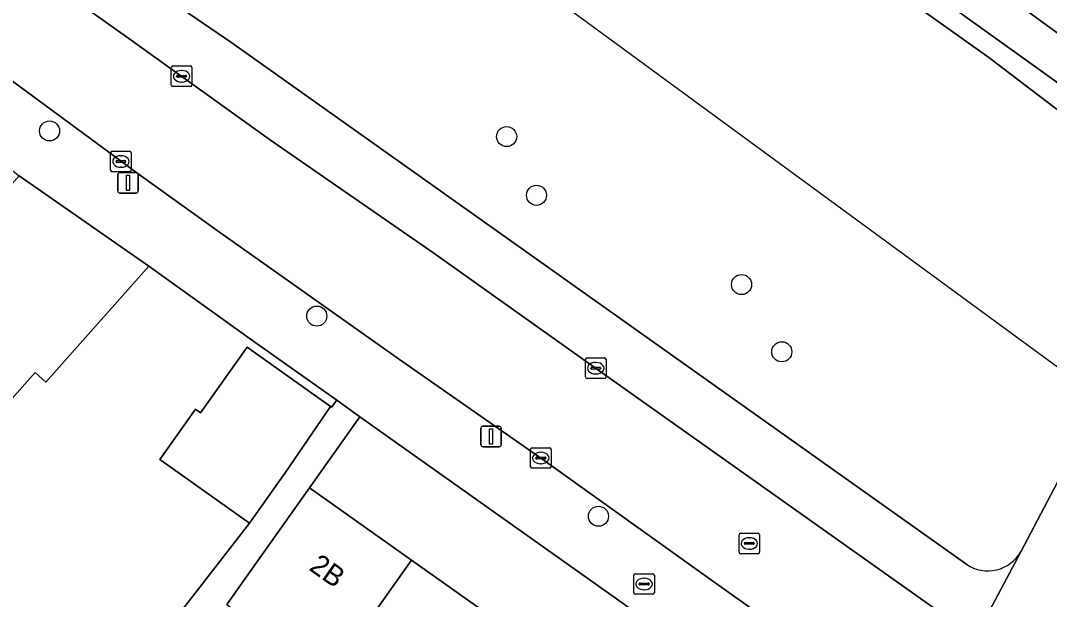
# Model space of a CAD drawing. Extents: x 162803 to 163818, y 381639 to 382475.
# Drawn here: x 162952.8 to 163002.9, y 382037.7 to 382065.9 of the extents above; entities that cross this region are included whole.
import ezdxf

# ---------------------------------------------------------------- set-up
doc = ezdxf.new("R2010")
doc.units = 0
for name, color, linetype in [('IMGEO_Boom', 7, 'Continuous'), ('IMGEO_Brandkraan', 7, 'Continuous'), ('IMGEO_Duiker', 7, 'Continuous'), ('IMGEO_Erf', 7, 'Continuous'), ('IMGEO_Groenvoorziening', 7, 'Continuous'), ('IMGEO_Haag', 7, 'Continuous'), ('IMGEO_Kolk', 7, 'Continuous'), ('IMGEO_Lichtmast', 7, 'Continuous'), ('IMGEO_Pand', 7, 'Continuous'), ('IMGEO_Pand_nummerreeks', 7, 'Continuous'), ('IMGEO_Rijbaan_lokaal_open', 7, 'Continuous'), ('IMGEO_Rioolput', 7, 'Continuous'), ('IMGEO_Voetpad_gesloten', 7, 'Continuous'), ('IMGEO_Voetpad_open', 7, 'Continuous')]:
    doc.layers.add(name, color=color, linetype=linetype)

msp = doc.modelspace()

# ---------------------------------------------------------------- linework, layer by layer
at = {"layer": 'IMGEO_Boom'}
for centre in [(162954.211, 382060.563), (162976.49, 382060.288), (162977.945, 382057.429), (162987.94, 382053.084), (162967.237, 382051.546), (162989.901, 382049.806), (162980.966, 382041.796)]:
    msp.add_circle(centre, 0.489, dxfattribs=at)
at = {"layer": 'IMGEO_Brandkraan'}
for p, q in [((162982.69, 382038.07), (162982.69, 382038.922)), ((162982.765, 382038.996), (162983.617, 382038.996)), ((162983.178, 382038.776), (162983.203, 382038.776)), ((162983.691, 382038.922), (162983.691, 382038.07)), ((162982.949, 382038.49), (162982.949, 382038.502)), ((162983.387, 382038.453), (162982.989, 382038.453)), ((162982.992, 382038.539), (162983.39, 382038.539)), ((162983.433, 382038.502), (162983.433, 382038.49)), ((162983.617, 382037.996), (162982.765, 382037.996)), ((162983.201, 382038.216), (162983.176, 382038.216))]:
    msp.add_line(p, q, dxfattribs=at)
for points in [[(162982.69, 382038.07), (162982.69, 382038.922)], [(162982.765, 382038.996), (162983.617, 382038.996)], [(162983.691, 382038.922), (162983.691, 382038.07)], [(162983.617, 382037.996), (162982.765, 382037.996)]]:
    msp.add_lwpolyline(points, dxfattribs=at)
for centre, radius, start, end in [((162982.767, 382038.92), 0.0765, 91.552, 178.448), ((162982.767, 382038.92), 0.0765, 91.552, 178.448), ((162983.615, 382038.92), 0.0765, 1.552, 88.448), ((162983.615, 382038.92), 0.0765, 1.552, 88.448), ((162982.989, 382038.499), 0.0403, 85.8775, 175.7526), ((162982.986, 382038.489), 0.0366, 178.938, 274.7102), ((162983.39, 382038.496), 0.043, 264.8664, 352.4533), ((162983.394, 382038.501), 0.0386, 1.7309, 96.639), ((162982.767, 382038.072), 0.0765, 181.552, 268.448), ((162982.767, 382038.072), 0.0765, 181.552, 268.448), ((162983.615, 382038.072), 0.0765, 271.552, 358.448), ((162983.615, 382038.072), 0.0765, 271.552, 358.448)]:
    msp.add_arc(centre, radius, start, end, dxfattribs=at)
for centre, major_axis, ratio, start_param, end_param in [((162983.177, 382038.496), (-0.387, 0.002), 0.722429, 4.712389, 7.853982), ((162983.202, 382038.496), (-0.39, 0.002), 0.717154, 1.570796, 4.712389)]:
    msp.add_ellipse(centre, major_axis=major_axis, ratio=ratio, start_param=start_param, end_param=end_param, dxfattribs=at)
at = {"layer": 'IMGEO_Duiker'}
msp.add_lwpolyline([(163005.466, 382047.505), (162974.599, 382070.108), (162970.901, 382072.816), (162970.703, 382072.961)], dxfattribs=at)
at = {"layer": 'IMGEO_Erf'}
msp.add_lwpolyline([(162958.614, 382034.766), (162959.507, 382035.735), (162963.96, 382041.461), (162959.584, 382044.562), (162961.318, 382047.008), (162961.57, 382046.829), (162963.835, 382050.026), (162967.902, 382047.144), (162967.96, 382047.103), (162968.205, 382047.449), (162964.058, 382050.389), (162959.047, 382053.976), (162954.036, 382048.329), (162953.503, 382048.802), (162949.504, 382044.283), (162949.355, 382044.115), (162945.432, 382039.695), (162941.189, 382034.913), (162937.377, 382030.619), (162933.576, 382026.335), (162932.914, 382025.589), (162929.595, 382021.849)], dxfattribs=at)
msp.add_lwpolyline([(162969.337, 382046.646), (162966.877, 382043.183), (162971.85, 382039.659), (162976.524, 382036.346), (162981.522, 382032.804), (162986.518, 382029.263), (162991.153, 382025.978), (162995.918, 382022.601), (163000, 382019.705), (163000.963, 382019.023), (163006.032, 382015.435), (163008.484, 382018.885), (163000, 382024.908)], close=True, dxfattribs=at)
at = {"layer": 'IMGEO_Groenvoorziening'}
for points in [[(163000, 382064.141), (162988.306, 382072.452), (162975.64, 382081.142), (162964.013, 382088.892), (162957.595, 382092.972), (162957.972, 382093.775), (162955.509, 382095.286), (162955.095, 382094.405), (162947.756, 382098.312), (162942.304, 382100.629), (162935.833, 382102.859), (162935.503, 382103.431), (162934.025, 382103.793), (162930.797, 382104.582), (162926.669, 382103.516), (162926.014, 382103.347), (162923.417, 382102.535), (162923.386, 382102.523), (162920.985, 382101.569), (162918.543, 382100.297)], [(162955.06, 382095.576), (162955.509, 382095.286), (162957.972, 382093.775), (162966.406, 382088.6), (162979.279, 382080.171), (163010.771, 382057.59), (163010.938, 382058.34)], [(162917.77, 382093.992), (162952.869, 382071.831), (162963.101, 382064.851), (162998.912, 382039.447)], [(163010.057, 382060.459), (162995.864, 382070.771)], [(163001.555, 382040.071), (163005.466, 382047.505), (163010.153, 382056.414), (163000, 382064.141)]]:
    msp.add_lwpolyline(points, dxfattribs=at)
msp.add_lwpolyline([(162979.279, 382080.171), (162966.406, 382088.6), (162957.972, 382093.775), (162957.595, 382092.972), (162964.013, 382088.892), (162975.64, 382081.142), (162988.306, 382072.452), (163000, 382064.141), (163010.153, 382056.414), (163010.771, 382057.59)], close=True, dxfattribs=at)
msp.add_arc((162999.941, 382040.996), 1.86, 236.3975, 330.1705, dxfattribs=at)
at = {"layer": 'IMGEO_Haag'}
msp.add_lwpolyline([(162979.279, 382080.171), (162966.406, 382088.6), (162957.972, 382093.775), (162957.595, 382092.972), (162964.013, 382088.892), (162975.64, 382081.142), (162988.306, 382072.452), (163000, 382064.141), (163010.153, 382056.414), (163010.771, 382057.59)], close=True, dxfattribs=at)
at = {"layer": 'IMGEO_Kolk'}
for p, q in [((162960.146, 382062.801), (162960.146, 382063.653)), ((162960.221, 382063.727), (162961.073, 382063.727)), ((162960.634, 382063.507), (162960.659, 382063.507)), ((162961.147, 382063.653), (162961.147, 382062.801)), ((162960.405, 382063.221), (162960.405, 382063.233)), ((162960.843, 382063.184), (162960.445, 382063.184)), ((162960.448, 382063.27), (162960.846, 382063.27)), ((162960.657, 382062.947), (162960.632, 382062.947)), ((162960.889, 382063.233), (162960.889, 382063.221)), ((162961.073, 382062.727), (162960.221, 382062.727)), ((162957.188, 382058.65), (162957.188, 382059.502)), ((162957.263, 382059.576), (162958.115, 382059.576)), ((162957.676, 382059.356), (162957.701, 382059.356)), ((162958.189, 382059.502), (162958.189, 382058.65)), ((162957.447, 382059.07), (162957.447, 382059.082)), ((162957.885, 382059.033), (162957.487, 382059.033)), ((162957.49, 382059.119), (162957.888, 382059.119)), ((162957.699, 382058.796), (162957.674, 382058.796)), ((162957.931, 382059.082), (162957.931, 382059.07)), ((162958.115, 382058.576), (162957.263, 382058.576)), ((162980.333, 382048.581), (162980.333, 382049.433)), ((162980.408, 382049.507), (162981.26, 382049.507)), ((162980.821, 382049.287), (162980.846, 382049.287)), ((162981.334, 382049.433), (162981.334, 382048.581)), ((162980.592, 382049.001), (162980.592, 382049.013)), ((162981.03, 382048.964), (162980.632, 382048.964)), ((162980.635, 382049.05), (162981.033, 382049.05)), ((162981.076, 382049.013), (162981.076, 382049.001)), ((162981.26, 382048.507), (162980.408, 382048.507)), ((162980.844, 382048.727), (162980.819, 382048.727)), ((162977.655, 382044.208), (162977.655, 382045.06)), ((162977.73, 382045.134), (162978.582, 382045.134)), ((162978.143, 382044.914), (162978.168, 382044.914)), ((162978.656, 382045.06), (162978.656, 382044.208)), ((162977.914, 382044.628), (162977.914, 382044.64)), ((162978.352, 382044.591), (162977.954, 382044.591)), ((162977.957, 382044.677), (162978.355, 382044.677)), ((162978.166, 382044.354), (162978.141, 382044.354)), ((162978.398, 382044.64), (162978.398, 382044.628)), ((162978.582, 382044.134), (162977.73, 382044.134))]:
    msp.add_line(p, q, dxfattribs=at)
for points in [[(162960.146, 382062.801), (162960.146, 382063.653)], [(162960.221, 382063.727), (162961.073, 382063.727)], [(162961.147, 382063.653), (162961.147, 382062.801)], [(162961.073, 382062.727), (162960.221, 382062.727)], [(162957.188, 382058.65), (162957.188, 382059.502)], [(162957.263, 382059.576), (162958.115, 382059.576)], [(162958.189, 382059.502), (162958.189, 382058.65)], [(162958.115, 382058.576), (162957.263, 382058.576)], [(162980.333, 382048.581), (162980.333, 382049.433)], [(162980.408, 382049.507), (162981.26, 382049.507)], [(162981.334, 382049.433), (162981.334, 382048.581)], [(162981.26, 382048.507), (162980.408, 382048.507)], [(162977.655, 382044.208), (162977.655, 382045.06)], [(162977.73, 382045.134), (162978.582, 382045.134)], [(162978.656, 382045.06), (162978.656, 382044.208)], [(162978.582, 382044.134), (162977.73, 382044.134)]]:
    msp.add_lwpolyline(points, dxfattribs=at)
for centre, radius, start, end in [((162960.223, 382063.651), 0.0765, 91.552, 178.448), ((162960.223, 382063.651), 0.0765, 91.552, 178.448), ((162961.071, 382063.651), 0.0765, 1.552, 88.448), ((162961.071, 382063.651), 0.0765, 1.552, 88.448), ((162960.445, 382063.23), 0.0403, 85.8775, 175.7526), ((162960.442, 382063.22), 0.0366, 178.938, 274.7102), ((162960.846, 382063.227), 0.043, 264.8664, 352.4533), ((162960.85, 382063.232), 0.0386, 1.7309, 96.639), ((162960.223, 382062.803), 0.0765, 181.552, 268.448), ((162960.223, 382062.803), 0.0765, 181.552, 268.448), ((162961.071, 382062.803), 0.0765, 271.552, 358.448), ((162961.071, 382062.803), 0.0765, 271.552, 358.448), ((162957.265, 382059.5), 0.0765, 91.552, 178.448), ((162957.265, 382059.5), 0.0765, 91.552, 178.448), ((162958.113, 382059.5), 0.0765, 1.552, 88.448), ((162958.113, 382059.5), 0.0765, 1.552, 88.448), ((162957.487, 382059.079), 0.0403, 85.8775, 175.7526), ((162957.484, 382059.069), 0.0366, 178.938, 274.7102), ((162957.888, 382059.076), 0.043, 264.8664, 352.4533), ((162957.892, 382059.081), 0.0386, 1.7309, 96.639), ((162957.265, 382058.652), 0.0765, 181.552, 268.448), ((162957.265, 382058.652), 0.0765, 181.552, 268.448), ((162958.113, 382058.652), 0.0765, 271.552, 358.448), ((162958.113, 382058.652), 0.0765, 271.552, 358.448), ((162980.41, 382049.431), 0.0765, 91.552, 178.448), ((162980.41, 382049.431), 0.0765, 91.552, 178.448), ((162981.258, 382049.431), 0.0765, 1.552, 88.448), ((162981.258, 382049.431), 0.0765, 1.552, 88.448), ((162980.632, 382049.01), 0.0403, 85.8775, 175.7526), ((162980.629, 382049), 0.0366, 178.938, 274.7102), ((162981.033, 382049.007), 0.043, 264.8664, 352.4533), ((162981.037, 382049.012), 0.0386, 1.7309, 96.639), ((162980.41, 382048.583), 0.0765, 181.552, 268.448), ((162980.41, 382048.583), 0.0765, 181.552, 268.448), ((162981.258, 382048.583), 0.0765, 271.552, 358.448), ((162981.258, 382048.583), 0.0765, 271.552, 358.448), ((162977.732, 382045.058), 0.0765, 91.552, 178.448), ((162977.732, 382045.058), 0.0765, 91.552, 178.448), ((162978.58, 382045.058), 0.0765, 1.552, 88.448), ((162978.58, 382045.058), 0.0765, 1.552, 88.448), ((162977.954, 382044.637), 0.0403, 85.8775, 175.7526), ((162977.951, 382044.627), 0.0366, 178.938, 274.7102), ((162978.355, 382044.634), 0.043, 264.8664, 352.4533), ((162978.359, 382044.639), 0.0386, 1.7309, 96.639), ((162977.732, 382044.21), 0.0765, 181.552, 268.448), ((162977.732, 382044.21), 0.0765, 181.552, 268.448), ((162978.58, 382044.21), 0.0765, 271.552, 358.448), ((162978.58, 382044.21), 0.0765, 271.552, 358.448)]:
    msp.add_arc(centre, radius, start, end, dxfattribs=at)
for centre, major_axis, ratio, start_param, end_param in [((162960.633, 382063.227), (-0.387, 0.002), 0.722429, 4.712389, 7.853982), ((162960.658, 382063.227), (-0.39, 0.002), 0.717154, 1.570796, 4.712389), ((162957.675, 382059.076), (-0.387, 0.002), 0.722429, 4.712389, 7.853982), ((162957.7, 382059.076), (-0.39, 0.002), 0.717154, 1.570796, 4.712389), ((162980.82, 382049.007), (-0.387, 0.002), 0.722429, 4.712389, 7.853982), ((162980.845, 382049.007), (-0.39, 0.002), 0.717154, 1.570796, 4.712389), ((162978.142, 382044.634), (-0.387, 0.002), 0.722429, 4.712389, 7.853982), ((162978.167, 382044.634), (-0.39, 0.002), 0.717154, 1.570796, 4.712389)]:
    msp.add_ellipse(centre, major_axis=major_axis, ratio=ratio, start_param=start_param, end_param=end_param, dxfattribs=at)
at = {"layer": 'IMGEO_Lichtmast'}
for p, q in [((162957.536, 382057.64), (162957.536, 382058.44)), ((162957.536, 382058.44), (162957.536, 382057.64)), ((162957.636, 382058.54), (162958.426, 382058.54)), ((162958.426, 382058.54), (162957.636, 382058.54)), ((162958.526, 382058.44), (162958.526, 382057.64)), ((162958.526, 382057.64), (162958.526, 382058.44)), ((162958.426, 382057.54), (162957.636, 382057.54)), ((162957.636, 382057.54), (162958.426, 382057.54)), ((162975.233, 382045.28), (162975.233, 382046.08)), ((162975.233, 382046.08), (162975.233, 382045.28)), ((162975.333, 382046.18), (162976.123, 382046.18)), ((162976.123, 382046.18), (162975.333, 382046.18)), ((162976.223, 382046.08), (162976.223, 382045.28)), ((162976.223, 382045.28), (162976.223, 382046.08)), ((162976.123, 382045.18), (162975.333, 382045.18)), ((162975.333, 382045.18), (162976.123, 382045.18))]:
    msp.add_line(p, q, dxfattribs=at)
for points in [[(162957.956, 382058.415), (162958.106, 382058.415), (162958.106, 382057.665), (162957.956, 382057.665), (162957.956, 382058.415)], [(162975.653, 382046.055), (162975.803, 382046.055), (162975.803, 382045.305), (162975.653, 382045.305), (162975.653, 382046.055)]]:
    msp.add_lwpolyline(points, dxfattribs=at)
for centre, start, end in [((162957.636, 382058.44), 90, 180), ((162957.636, 382058.44), 90, 180), ((162958.426, 382058.44), 0, 90), ((162958.426, 382058.44), 360, 90), ((162957.636, 382057.64), 180, 270), ((162957.636, 382057.64), 180, 270), ((162958.426, 382057.64), 270, 0), ((162958.426, 382057.64), 270, 0), ((162975.333, 382046.08), 90, 180), ((162975.333, 382046.08), 90, 180), ((162976.123, 382046.08), 0, 90), ((162976.123, 382046.08), 360, 90), ((162975.333, 382045.28), 180, 270), ((162975.333, 382045.28), 180, 270), ((162976.123, 382045.28), 270, 0), ((162976.123, 382045.28), 270, 0)]:
    msp.add_arc(centre, 0.1, start, end, dxfattribs=at)
at = {"layer": 'IMGEO_Pand'}
for points in [[(162959.047, 382053.976), (162952.728, 382058.385), (162948.312, 382053.409), (162944.157, 382048.727), (162949.355, 382044.115), (162949.504, 382044.283), (162953.503, 382048.802), (162954.036, 382048.329)], [(162967.902, 382047.144), (162963.835, 382050.026), (162961.57, 382046.829), (162961.318, 382047.008), (162959.584, 382044.562), (162963.96, 382041.461), (162965.694, 382043.907)], [(162971.85, 382039.659), (162966.877, 382043.183), (162963.986, 382039.104), (162962.847, 382037.497), (162967.82, 382033.973)], [(162971.85, 382039.659), (162967.82, 382033.973), (162972.494, 382030.66), (162976.524, 382036.346)]]:
    msp.add_lwpolyline(points, close=True, dxfattribs=at)
at = {"layer": 'IMGEO_Rijbaan_lokaal_open'}
for points in [[(163000, 382035.427), (162999.338, 382035.896), (162980.876, 382048.976), (162972.946, 382054.612), (162964.986, 382060.117), (162957.956, 382065.153), (162955.06, 382067.225), (162953.532, 382068.186), (162947.68, 382072.11), (162941.476, 382076.103), (162935.644, 382079.686), (162923.06, 382087.554), (162918.151, 382090.703), (162915.515, 382092.326), (162915.051, 382092.68)], [(162924.094, 382080.905), (162925.141, 382080.252), (162940.646, 382070.58), (162940.946, 382070.393), (162944.453, 382068.159), (162951.044, 382063.961), (162951.212, 382063.853), (162958.651, 382058.394), (162962.384, 382055.718), (162963.554, 382054.88), (162965.988, 382053.161), (162971.264, 382049.436), (162978.206, 382044.6), (162986.475, 382038.685), (163000, 382029.075), (163041.126, 382000), (163087.644, 381967.002), (163090.633, 381971.241), (163086.515, 381974.156), (163077.734, 381980.369), (163049.995, 382000), (163031.46, 382013.134), (163017.878, 382022.758), (163000, 382035.427)]]:
    msp.add_lwpolyline(points, dxfattribs=at)
at = {"layer": 'IMGEO_Rioolput'}
for p, q in [((162987.816, 382040.046), (162987.816, 382040.898)), ((162987.891, 382040.972), (162988.743, 382040.972)), ((162988.304, 382040.752), (162988.329, 382040.752)), ((162988.817, 382040.898), (162988.817, 382040.046)), ((162988.075, 382040.466), (162988.075, 382040.478)), ((162988.513, 382040.429), (162988.115, 382040.429)), ((162988.118, 382040.515), (162988.516, 382040.515)), ((162988.559, 382040.478), (162988.559, 382040.466)), ((162988.743, 382039.972), (162987.891, 382039.972)), ((162988.327, 382040.192), (162988.302, 382040.192))]:
    msp.add_line(p, q, dxfattribs=at)
for points in [[(162987.816, 382040.046), (162987.816, 382040.898)], [(162987.891, 382040.972), (162988.743, 382040.972)], [(162988.817, 382040.898), (162988.817, 382040.046)], [(162988.743, 382039.972), (162987.891, 382039.972)]]:
    msp.add_lwpolyline(points, dxfattribs=at)
for centre, radius, start, end in [((162987.893, 382040.896), 0.0765, 91.552, 178.448), ((162987.893, 382040.896), 0.0765, 91.552, 178.448), ((162988.741, 382040.896), 0.0765, 1.552, 88.448), ((162988.741, 382040.896), 0.0765, 1.552, 88.448), ((162988.115, 382040.475), 0.0403, 85.8775, 175.7526), ((162988.112, 382040.465), 0.0366, 178.938, 274.7102), ((162988.516, 382040.472), 0.043, 264.8664, 352.4533), ((162988.52, 382040.477), 0.0386, 1.7309, 96.639), ((162987.893, 382040.048), 0.0765, 181.552, 268.448), ((162987.893, 382040.048), 0.0765, 181.552, 268.448), ((162988.741, 382040.048), 0.0765, 271.552, 358.448), ((162988.741, 382040.048), 0.0765, 271.552, 358.448)]:
    msp.add_arc(centre, radius, start, end, dxfattribs=at)
for centre, major_axis, ratio, start_param, end_param in [((162988.303, 382040.472), (-0.387, 0.002), 0.722429, 4.712389, 7.853982), ((162988.328, 382040.472), (-0.39, 0.002), 0.717154, 1.570796, 4.712389)]:
    msp.add_ellipse(centre, major_axis=major_axis, ratio=ratio, start_param=start_param, end_param=end_param, dxfattribs=at)
at = {"layer": 'IMGEO_Voetpad_gesloten'}
msp.add_lwpolyline([(163003.377, 382038.062), (163006.306, 382043.606), (163007.557, 382045.975), (163012.449, 382055.286), (163012.993, 382056.322), (163014.754, 382059.7), (163016.465, 382062.979), (163014.396, 382064.481), (163012.658, 382061.177), (163010.771, 382057.59), (163010.153, 382056.414), (163005.466, 382047.505), (163001.555, 382040.071), (162999.764, 382036.698), (163018.398, 382023.492), (163018.116, 382023.094), (163032.377, 382017.185), (163034.633, 382016.251), (163063.928, 382003.918)], dxfattribs=at)
at = {"layer": 'IMGEO_Voetpad_open'}
for points in [[(162916.802, 382096.204), (162915.051, 382092.68), (162915.515, 382092.326), (162918.151, 382090.703), (162923.06, 382087.554), (162935.644, 382079.686), (162941.476, 382076.103), (162947.68, 382072.11), (162953.532, 382068.186), (162955.06, 382067.225), (162957.956, 382065.153), (162964.986, 382060.117), (162972.946, 382054.612), (162980.876, 382048.976), (162999.338, 382035.896), (162999.764, 382036.698), (163001.555, 382040.071)], [(162923.812, 382076.99), (162939.702, 382067.058), (162943.583, 382064.624), (162947.554, 382062.095), (162951.948, 382058.979), (162951.991, 382058.949), (162952.728, 382058.385), (162959.047, 382053.976), (162964.058, 382050.389), (162968.205, 382047.449), (162969.337, 382046.646), (163000, 382024.908), (163008.484, 382018.885), (163010.924, 382017.152), (163035.082, 382000), (163083.894, 381965.344), (163085.162, 381964.444), (163087.923, 381962.484), (163087.934, 381962.5), (163090.134, 381960.942), (163090.121, 381960.923), (163102.928, 381951.83)], [(162998.912, 382039.447), (162963.101, 382064.851), (162952.869, 382071.831)], [(163000, 382029.075), (162986.475, 382038.685), (162978.206, 382044.6), (162971.264, 382049.436), (162965.988, 382053.161), (162963.554, 382054.88), (162962.384, 382055.718), (162958.651, 382058.394), (162951.212, 382063.853), (162951.044, 382063.961), (162950.485, 382063.084), (162943.894, 382067.282), (162944.453, 382068.159), (162940.946, 382070.393), (162940.646, 382070.58)], [(162995.864, 382070.771), (163010.057, 382060.459)], [(162962.847, 382037.497), (162963.986, 382039.104), (162966.877, 382043.183), (162969.337, 382046.646), (162968.205, 382047.449), (162967.96, 382047.103), (162967.902, 382047.144), (162965.694, 382043.907), (162963.96, 382041.461), (162959.507, 382035.735)]]:
    msp.add_lwpolyline(points, dxfattribs=at)
msp.add_arc((162999.941, 382040.996), 1.86, 236.3975, 330.1705, dxfattribs=at)

# ---------------------------------------------------------------- texts
at = {"layer": 'IMGEO_Pand_nummerreeks'}
msp.add_text('2B', height=1, rotation=324.674, dxfattribs=at).set_placement((162966.811, 382039.21))

doc.saveas('drawing.dxf')
